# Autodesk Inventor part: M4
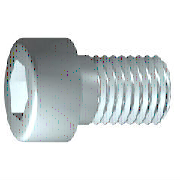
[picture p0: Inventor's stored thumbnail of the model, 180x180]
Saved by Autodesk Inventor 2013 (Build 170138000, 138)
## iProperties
IsCustomPart: 0
Created: 2016-04
Part Number: M4
Material: 강철, 연강
Description: 6각머리 태핑 나사
Document SubType Name: Modeling
Standard: KS B 1003
Designer: mdu
Standards Organization: KS
Language: ko-KR
Size Designation: M 4 x 10
Categories: <MemberInstance><Categories><Category DisplayName="조임쇠" InternalName="e4da775c-781d-43d5-af7c-5136215cf5a6" Mnemonic="FSTN"><Category DisplayName="볼트" InternalN
Density: 7.86 g/cm^3
Mass: 2.0371 g
Surface Area: 3.0572 cm^2
Volume: 0.259174 cm^3
Author: mdu
Revision Number: 1
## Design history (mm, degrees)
sketch "스케치1"
  geometry: L1 (-1, 0)-(10, 0); L2 (10, 0)-(10, 2); L3 (10, 2)-(1.75, 2); L4 (1.75, 2)-(1.32, 2); L5 (1.32, 2)-(0, 2); L6 (0, 2)-(0, 3.5); L7 (0, 3.5)-(-4, 3.5); L8 (-4, 3.5)-(-4, 1.732); L9 (-4, 1.732)-(-2, 1.732); L10 (-2, 1.732)-(-1, 0); L11 (-6.8, 0)-(12.8, 0) reference; L12 (0, -0.7)-(0, 4.2) reference; L13 (1.75, 2)-(0, 2)
  constraints: 22 end point, 6 parallel, 2 collinear, 2 perpendicular, 1 horizontal, 1 point on line
  dimensions: "d1" = 8.25 distance from line of L3.end L2 (= GEL); "d2" = 0.42952 distance of L4.end L3.end (computed from GAL); "d3" = 4 distance between parallel lines of L8 L6 (= KOH); "d4" = 2 distance of L8.end L9.end (= INTI); "d5" = 60 deg angle of L10 L1; "d6" = 4 diameter of L3 L1 (= GD); "d7" = 4 diameter of L5 L1 (= BDM); "d8" = 3.4641 diameter of L9 L1 (= 1.1547 x SW); "d9" = 7 diameter of L7 L1 (= KOD); "d26" = 10 distance between parallel lines of L12 L2 (= NLG)
revolve "본체" sketch "스케치1" stored, may be unused: angle "d10" = 90 deg
sketch "스케치2"
  geometry: L1 (0, -4.9)-(0, 4.9) reference; L2 (-4.9, 0)-(4.9, 0) reference; L3 (1.732, 0)-(0.866, -1.5); L4 (0.866, -1.5)-(-0.866, -1.5); L5 (-0.866, -1.5)-(-1.732, 0); L6 (-1.732, 0)-(-0.866, 1.5); L7 (-0.866, 1.5)-(0.866, 1.5); L8 (0.866, 1.5)-(1.732, 0); 2 further points
  constraints: 12 end point, 1 coincident, 1 horizontal alignment, 1 point on line, 12 other
extrude "슬롯" join sketch "스케치2" stored distance "d11" = 10; taper "d12" = 0 deg
workplane "Work Plane1"
fillet "Fillet2" dims "d30" = 0.1 (= R)
body "Solid1"
fillet "모깎기1" dims "d17" = 0.4 (= RR)
feature "스레드" dims "d13" = 8.25 (= GEL), "d14" = 0
chamfer "모따기1" distance "d15" = 0.42941 (= -0.5 x SPD + 0.5 x GD); stored, may be unused: second distance "d16" = 0.42941 (= GUL), angle "d27" = 45 deg
other parameters: "GD" = 4 (= NND) [user parameter; used in 2 equation terms], "NLG" = 10 [user parameter; used in 1 equation term], "GEL" = 8.25 [user parameter; used in 2 equation terms], "KOD" = 7 [user parameter; used in 1 equation term], "KOH" = 4 [user parameter; used in 1 equation term], "INTI" = 2 [user parameter; used in 1 equation term], "GAL" = 0.42941 (= 0.61345 x PTC) [user parameter; used in 1 equation term], "GUL" = 0.42941 (= 0.61345 x PTC) [user parameter; used in 1 equation term], "BDM" = 4 (= NND) [user parameter; used in 1 equation term], "SW" = 3 [user parameter; used in 2 equation terms], "RR" = 0.4 [user parameter; used in 1 equation term], "SPD" = 3.14117 (= NND - 1.2269 x PTC) [user parameter; used in 1 equation term], "d19" = 0, "d28" = 0, "d29" = 0, "R" = 0.1 [user parameter; used in 1 equation term], "PHH" = 0.2 [user parameter], "GD1" = 3.14117 (= THREADDIA - 1.2269 x PTC) [user parameter], "THREADDIA" = 4 [user parameter; used in 1 equation term], "FAWI" = 45 deg [user parameter], "TPU" = 14.28571 (computed from PTC) [user parameter], "PTC" = 0.7 [user parameter; used in 5 equation terms], "NND" = 4 [user parameter; used in 3 equation terms], "TOA" = 30 deg [user parameter], "E0" = 3.465 (= 1.155 x SW) [user parameter]
